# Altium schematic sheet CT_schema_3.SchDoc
size 287 x 169 mm
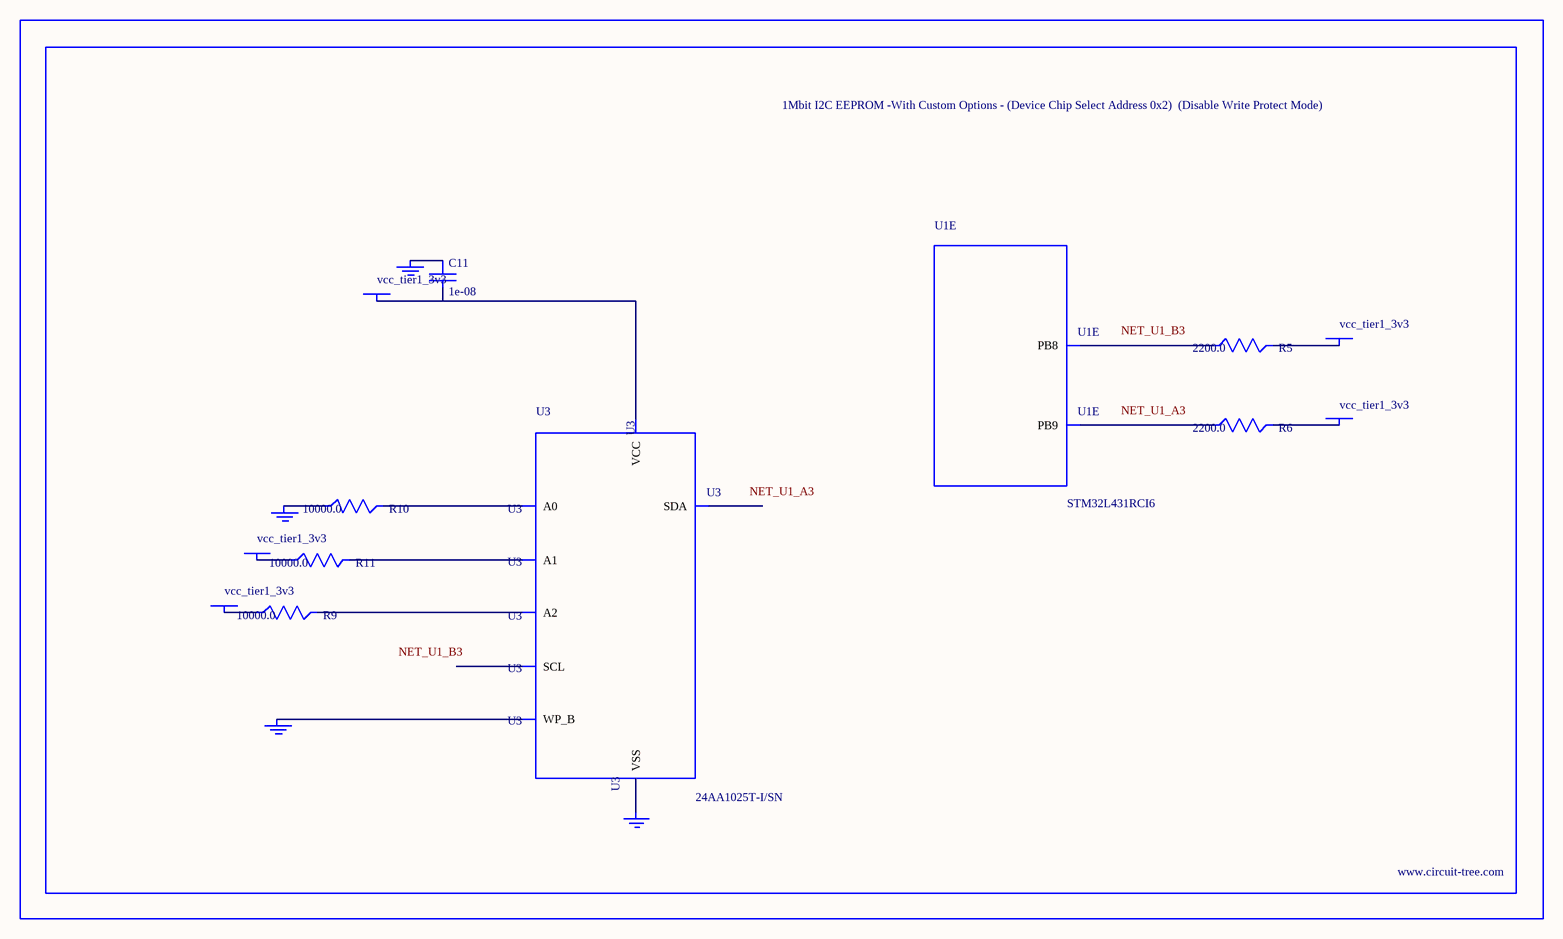
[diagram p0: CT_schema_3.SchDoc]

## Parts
BORDER2  (no value)
C11  1e-08  [C0402]
GND_INSTANCE_2_0  (no value)
GND_INSTANCE_2_1  (no value)
GND_INSTANCE_2_2  (no value)
GND_INSTANCE_2_3  (no value)
POWER_INSTANCE_2_0  vcc_tier1_3v3
POWER_INSTANCE_2_1  vcc_tier1_3v3
POWER_INSTANCE_2_2  vcc_tier1_3v3
POWER_INSTANCE_2_3  vcc_tier1_3v3
POWER_INSTANCE_2_4  vcc_tier1_3v3
R5  2200.0  [R0603]
R6  2200.0  [R0603]
R9  10000.0  [R0603]
R10  10000.0  [R0603]
R11  10000.0  [R0603]
U1  STM32L431RCI6  [UFBGA64]  (part E of 6)
U3  24AA1025T-I/SN  [SOIC-8]

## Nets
NetC11_1: C11.1 GND_INSTANCE_2_2.0(GND)
NetC11_2: C11.2 POWER_INSTANCE_2_2.0(PWR) U3.8(VCC)
NetGND_INSTANCE_2_0_0: GND_INSTANCE_2_0.0(GND) R10.1
NetGND_INSTANCE_2_1_0: GND_INSTANCE_2_1.0(GND) U3.7(WP_B)
NetGND_INSTANCE_2_3_0: GND_INSTANCE_2_3.0(GND) U3.4(VSS)
NetPOWER_INSTANCE_2_0_0: POWER_INSTANCE_2_0.0(PWR) R11.1
NetPOWER_INSTANCE_2_1_0: POWER_INSTANCE_2_1.0(PWR) R9.1
NetPOWER_INSTANCE_2_3_0: POWER_INSTANCE_2_3.0(PWR) R5.2
NetPOWER_INSTANCE_2_4_0: POWER_INSTANCE_2_4.0(PWR) R6.2
NetR5_1: R5.1 U1.B3(PB8)
NetR6_1: R6.1 U1.A3(PB9)
NetR9_2: R9.2 U3.3(A2)
NetR10_2: R10.2 U3.1(A0)
NetR11_2: R11.2 U3.2(A1)

Not connected (* = marked no-connect by the designer): U3 5(SDA) 6(SCL)

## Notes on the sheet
- Labels drawn without touching a wire or pin: NET_U1_A3, NET_U1_B3

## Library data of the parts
BORDER2 = BORDER_PAGE2
C11 = C0402C103K3RAC
GND_INSTANCE_2_0-GND_INSTANCE_2_3 = GND
POWER_INSTANCE_2_0-POWER_INSTANCE_2_4 = PWR
R5 R6 = RC0603JR-072K2L
R9-R11 = RC0603JR-0710KL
